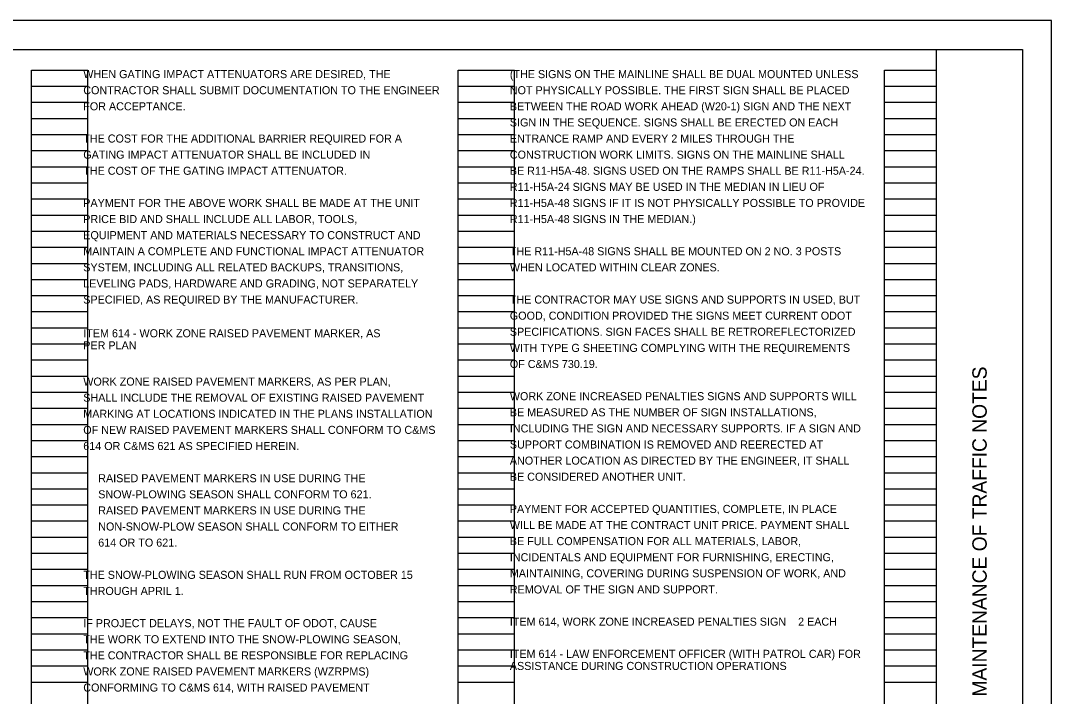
# Model space of a CAD drawing. Extents: x 0 to 34, y 0 to 22.
# Drawn here: x 16.07 to 34, y 10.25 to 22 of the extents above; entities that cross this region are included whole.
import ezdxf

# ---------------------------------------------------------------- set-up
doc = ezdxf.new("R2010")
doc.units = 0
for name, color, linetype in [('SH_Border', 7, 'Continuous'), ('SH_Cut_Line', 7, 'Continuous'), ('SH_Data', 7, 'Continuous'), ('SH_Text', 7, 'Continuous')]:
    doc.layers.add(name, color=color, linetype=linetype)

msp = doc.modelspace()

# ---------------------------------------------------------------- linework, layer by layer
at = {"layer": 'SH_Border'}
msp.add_line((32, 0.5), (32, 21.5), dxfattribs=at)
msp.add_lwpolyline([(1.5, 21.5), (33.5, 21.5), (33.5, 0.5), (1.5, 0.5)], close=True, dxfattribs=at)
at = {"layer": 'SH_Cut_Line'}
msp.add_lwpolyline([(0, 0), (34, 0), (34, 22), (0, 22)], close=True, dxfattribs=at)
at = {"layer": 'SH_Data'}
for p, q in [((16.26, 0.98), (16.26, 21.14)), ((16.26, 21.14), (17.24, 21.14)), ((17.24, 0.98), (17.24, 21.14)), ((23.68, 0.98), (23.68, 21.14)), ((23.68, 21.14), (24.66, 21.14)), ((24.66, 0.98), (24.66, 21.14)), ((31.1, 0.98), (31.1, 21.14)), ((31.1, 21.14), (32, 21.14)), ((32, 0.98), (32, 21.14)), ((16.26, 20.86), (17.24, 20.86)), ((23.68, 20.86), (24.66, 20.86)), ((31.1, 20.86), (32, 20.86)), ((16.26, 20.58), (17.24, 20.58)), ((23.68, 20.58), (24.66, 20.58)), ((31.1, 20.58), (32, 20.58)), ((16.26, 20.3), (17.24, 20.3)), ((23.68, 20.3), (24.66, 20.3)), ((31.1, 20.3), (32, 20.3)), ((16.26, 20.02), (17.24, 20.02)), ((23.68, 20.02), (24.66, 20.02)), ((31.1, 20.02), (32, 20.02)), ((16.26, 19.74), (17.24, 19.74)), ((23.68, 19.74), (24.66, 19.74)), ((31.1, 19.74), (32, 19.74)), ((16.26, 19.46), (17.24, 19.46)), ((23.68, 19.46), (24.66, 19.46)), ((31.1, 19.46), (32, 19.46)), ((16.26, 19.18), (17.24, 19.18)), ((23.68, 19.18), (24.66, 19.18)), ((31.1, 19.18), (32, 19.18)), ((16.26, 18.9), (17.24, 18.9)), ((23.68, 18.9), (24.66, 18.9)), ((31.1, 18.9), (32, 18.9)), ((16.26, 18.62), (17.24, 18.62)), ((23.68, 18.62), (24.66, 18.62)), ((31.1, 18.62), (32, 18.62)), ((16.26, 18.34), (17.24, 18.34)), ((23.68, 18.34), (24.66, 18.34)), ((31.1, 18.34), (32, 18.34)), ((16.26, 18.06), (17.24, 18.06)), ((23.68, 18.06), (24.66, 18.06)), ((31.1, 18.06), (32, 18.06)), ((16.26, 17.78), (17.24, 17.78)), ((23.68, 17.78), (24.66, 17.78)), ((31.1, 17.78), (32, 17.78)), ((16.26, 17.5), (17.24, 17.5)), ((23.68, 17.5), (24.66, 17.5)), ((31.1, 17.5), (32, 17.5)), ((16.26, 17.22), (17.24, 17.22)), ((23.68, 17.22), (24.66, 17.22)), ((31.1, 17.22), (32, 17.22)), ((16.26, 16.94), (17.24, 16.94)), ((23.68, 16.94), (24.66, 16.94)), ((31.1, 16.94), (32, 16.94)), ((16.26, 16.66), (17.24, 16.66)), ((23.68, 16.66), (24.66, 16.66)), ((31.1, 16.66), (32, 16.66)), ((16.26, 16.38), (17.24, 16.38)), ((23.68, 16.38), (24.66, 16.38)), ((31.1, 16.38), (32, 16.38)), ((16.26, 16.1), (17.24, 16.1)), ((23.68, 16.1), (24.66, 16.1)), ((31.1, 16.1), (32, 16.1)), ((16.26, 15.82), (17.24, 15.82)), ((23.68, 15.82), (24.66, 15.82)), ((31.1, 15.82), (32, 15.82)), ((16.26, 15.54), (17.24, 15.54)), ((23.68, 15.54), (24.66, 15.54)), ((31.1, 15.54), (32, 15.54)), ((16.26, 15.26), (17.24, 15.26)), ((23.68, 15.26), (24.66, 15.26)), ((31.1, 15.26), (32, 15.26)), ((16.26, 14.98), (17.24, 14.98)), ((23.68, 14.98), (24.66, 14.98)), ((31.1, 14.98), (32, 14.98)), ((16.26, 14.7), (17.24, 14.7)), ((23.68, 14.7), (24.66, 14.7)), ((31.1, 14.7), (32, 14.7)), ((16.26, 14.42), (17.24, 14.42)), ((23.68, 14.42), (24.66, 14.42)), ((31.1, 14.42), (32, 14.42)), ((16.26, 14.14), (17.24, 14.14)), ((23.68, 14.14), (24.66, 14.14)), ((31.1, 14.14), (32, 14.14)), ((16.26, 13.86), (17.24, 13.86)), ((23.68, 13.86), (24.66, 13.86)), ((31.1, 13.86), (32, 13.86)), ((16.26, 13.58), (17.24, 13.58)), ((23.68, 13.58), (24.66, 13.58)), ((31.1, 13.58), (32, 13.58)), ((16.26, 13.3), (17.24, 13.3)), ((23.68, 13.3), (24.66, 13.3)), ((31.1, 13.3), (32, 13.3)), ((16.26, 13.02), (17.24, 13.02)), ((23.68, 13.02), (24.66, 13.02)), ((31.1, 13.02), (32, 13.02)), ((16.26, 12.74), (17.24, 12.74)), ((23.68, 12.74), (24.66, 12.74)), ((31.1, 12.74), (32, 12.74)), ((16.26, 12.46), (17.24, 12.46)), ((23.68, 12.46), (24.66, 12.46)), ((31.1, 12.46), (32, 12.46)), ((16.26, 12.18), (17.24, 12.18)), ((23.68, 12.18), (24.66, 12.18)), ((31.1, 12.18), (32, 12.18)), ((16.26, 11.9), (17.24, 11.9)), ((23.68, 11.9), (24.66, 11.9)), ((31.1, 11.9), (32, 11.9)), ((16.26, 11.62), (17.24, 11.62)), ((23.68, 11.62), (24.66, 11.62)), ((31.1, 11.62), (32, 11.62)), ((16.26, 11.34), (17.24, 11.34)), ((23.68, 11.34), (24.66, 11.34)), ((31.1, 11.34), (32, 11.34)), ((16.26, 11.06), (17.24, 11.06)), ((23.68, 11.06), (24.66, 11.06)), ((31.1, 11.06), (32, 11.06)), ((16.26, 10.78), (17.24, 10.78)), ((23.68, 10.78), (24.66, 10.78)), ((31.1, 10.78), (32, 10.78)), ((16.26, 10.5), (17.24, 10.5)), ((23.68, 10.5), (24.66, 10.5)), ((31.1, 10.5), (32, 10.5))]:
    msp.add_line(p, q, dxfattribs=at)

# ---------------------------------------------------------------- texts
msp.add_text('MAINTENANCE OF TRAFFIC NOTES', height=0.25, rotation=90, dxfattribs=at).set_placement((32.875, 10.247))
at = {"layer": 'SH_Text'}
for s, p in [('WHEN GATING IMPACT ATTENUATORS ARE DESIRED, THE ', (17.16, 21)), ('(THE SIGNS ON THE MAINLINE SHALL BE DUAL MOUNTED UNLESS', (24.58, 21)), ('CONTRACTOR SHALL SUBMIT DOCUMENTATION TO THE ENGINEER ', (17.16, 20.72)), ('NOT PHYSICALLY POSSIBLE. THE FIRST SIGN SHALL BE PLACED', (24.58, 20.72)), ('FOR ACCEPTANCE. ', (17.16, 20.44)), ('BETWEEN THE ROAD WORK AHEAD (W20-1) SIGN AND THE NEXT', (24.58, 20.44)), ('SIGN IN THE SEQUENCE. SIGNS SHALL BE ERECTED ON EACH', (24.58, 20.16)), ('THE COST FOR THE ADDITIONAL BARRIER REQUIRED FOR A ', (17.16, 19.88)), ('ENTRANCE RAMP AND EVERY 2 MILES THROUGH THE', (24.58, 19.88)), ('GATING IMPACT ATTENUATOR SHALL BE INCLUDED IN ', (17.16, 19.6)), ('CONSTRUCTION WORK LIMITS. SIGNS ON THE MAINLINE SHALL', (24.58, 19.6)), ('THE COST OF THE GATING IMPACT ATTENUATOR. ', (17.16, 19.32)), ('BE R11-H5A-48. SIGNS USED ON THE RAMPS SHALL BE R11-H5A-24.', (24.58, 19.32)), ('R11-H5A-24 SIGNS MAY BE USED IN THE MEDIAN IN LIEU OF', (24.58, 19.04)), ('PAYMENT FOR THE ABOVE WORK SHALL BE MADE AT THE UNIT ', (17.16, 18.76)), ('R11-H5A-48 SIGNS IF IT IS NOT PHYSICALLY POSSIBLE TO PROVIDE', (24.58, 18.76)), ('PRICE BID AND SHALL INCLUDE ALL LABOR, TOOLS, ', (17.16, 18.48)), ('R11-H5A-48 SIGNS IN THE MEDIAN.)', (24.58, 18.48)), ('EQUIPMENT AND MATERIALS NECESSARY TO CONSTRUCT AND ', (17.16, 18.2)), ('MAINTAIN A COMPLETE AND FUNCTIONAL IMPACT ATTENUATOR ', (17.16, 17.92)), ('THE R11-H5A-48 SIGNS SHALL BE MOUNTED ON 2 NO. 3 POSTS', (24.58, 17.92)), ('SYSTEM, INCLUDING ALL RELATED BACKUPS, TRANSITIONS, ', (17.16, 17.64)), ('WHEN LOCATED WITHIN CLEAR ZONES.', (24.58, 17.64)), ('LEVELING PADS, HARDWARE AND GRADING, NOT SEPARATELY ', (17.16, 17.36)), ('SPECIFIED, AS REQUIRED BY THE MANUFACTURER.', (17.16, 17.08)), ('THE CONTRACTOR MAY USE SIGNS AND SUPPORTS IN USED, BUT', (24.58, 17.08)), ('GOOD, CONDITION PROVIDED THE SIGNS MEET CURRENT ODOT', (24.58, 16.8)), ('ITEM 614 - WORK ZONE RAISED PAVEMENT MARKER, AS ', (17.16, 16.494)), ('SPECIFICATIONS. SIGN FACES SHALL BE RETROREFLECTORIZED', (24.58, 16.52)), ('PER PLAN', (17.16, 16.284)), ('WITH TYPE G SHEETING COMPLYING WITH THE REQUIREMENTS', (24.58, 16.24)), ('OF C&MS 730.19.', (24.58, 15.96)), ('WORK ZONE RAISED PAVEMENT MARKERS, AS PER PLAN,', (17.16, 15.654)), ('SHALL INCLUDE THE REMOVAL OF EXISTING RAISED PAVEMENT ', (17.16, 15.374)), ('WORK ZONE INCREASED PENALTIES SIGNS AND SUPPORTS WILL', (24.58, 15.4)), ('BE MEASURED AS THE NUMBER OF SIGN INSTALLATIONS,', (24.58, 15.12)), ('MARKING AT LOCATIONS INDICATED IN THE PLANS INSTALLATION ', (17.16, 15.094)), ('OF NEW RAISED PAVEMENT MARKERS SHALL CONFORM TO C&MS ', (17.16, 14.814)), ('INCLUDING THE SIGN AND NECESSARY SUPPORTS. IF A SIGN AND', (24.58, 14.84)), ('614 OR C&MS 621 AS SPECIFIED HEREIN.', (17.16, 14.534)), ('SUPPORT COMBINATION IS REMOVED AND REERECTED AT', (24.58, 14.56)), ('ANOTHER LOCATION AS DIRECTED BY THE ENGINEER, IT SHALL', (24.58, 14.28)), ('     RAISED PAVEMENT MARKERS IN USE DURING THE', (17.16, 13.974)), ('BE CONSIDERED ANOTHER UNIT.', (24.58, 14)), ('     SNOW-PLOWING SEASON SHALL CONFORM TO 621.', (17.16, 13.694)), ('     RAISED PAVEMENT MARKERS IN USE DURING THE', (17.16, 13.414)), ('PAYMENT FOR ACCEPTED QUANTITIES, COMPLETE, IN PLACE', (24.58, 13.44)), ('     NON-SNOW-PLOW SEASON SHALL CONFORM TO EITHER', (17.16, 13.134)), ('WILL BE MADE AT THE CONTRACT UNIT PRICE. PAYMENT SHALL', (24.58, 13.16)), ('     614 OR TO 621.', (17.16, 12.854)), ('BE FULL COMPENSATION FOR ALL MATERIALS, LABOR,', (24.58, 12.88)), ('INCIDENTALS AND EQUIPMENT FOR FURNISHING, ERECTING,', (24.58, 12.6)), ('THE SNOW-PLOWING SEASON SHALL RUN FROM OCTOBER 15', (17.16, 12.294)), ('MAINTAINING, COVERING DURING SUSPENSION OF WORK, AND', (24.58, 12.32)), ('THROUGH APRIL 1.', (17.16, 12.014)), ('REMOVAL OF THE SIGN AND SUPPORT.', (24.58, 12.04)), ('IF PROJECT DELAYS, NOT THE FAULT OF ODOT, CAUSE', (17.16, 11.454)), ('ITEM 614, WORK ZONE INCREASED PENALTIES SIGN    2 EACH', (24.58, 11.48)), ('THE WORK TO EXTEND INTO THE SNOW-PLOWING SEASON,', (17.16, 11.174)), ('THE CONTRACTOR SHALL BE RESPONSIBLE FOR REPLACING', (17.16, 10.894)), ('ITEM 614 - LAW ENFORCEMENT OFFICER (WITH PATROL CAR) FOR ', (24.58, 10.92)), ('WORK ZONE RAISED PAVEMENT MARKERS (WZRPMS)', (17.16, 10.614)), ('ASSISTANCE DURING CONSTRUCTION OPERATIONS', (24.58, 10.71)), ('CONFORMING TO C&MS 614, WITH RAISED PAVEMENT', (17.16, 10.334))]:
    msp.add_text(s, height=0.14, dxfattribs=at).set_placement(p)

doc.saveas('drawing.dxf')
